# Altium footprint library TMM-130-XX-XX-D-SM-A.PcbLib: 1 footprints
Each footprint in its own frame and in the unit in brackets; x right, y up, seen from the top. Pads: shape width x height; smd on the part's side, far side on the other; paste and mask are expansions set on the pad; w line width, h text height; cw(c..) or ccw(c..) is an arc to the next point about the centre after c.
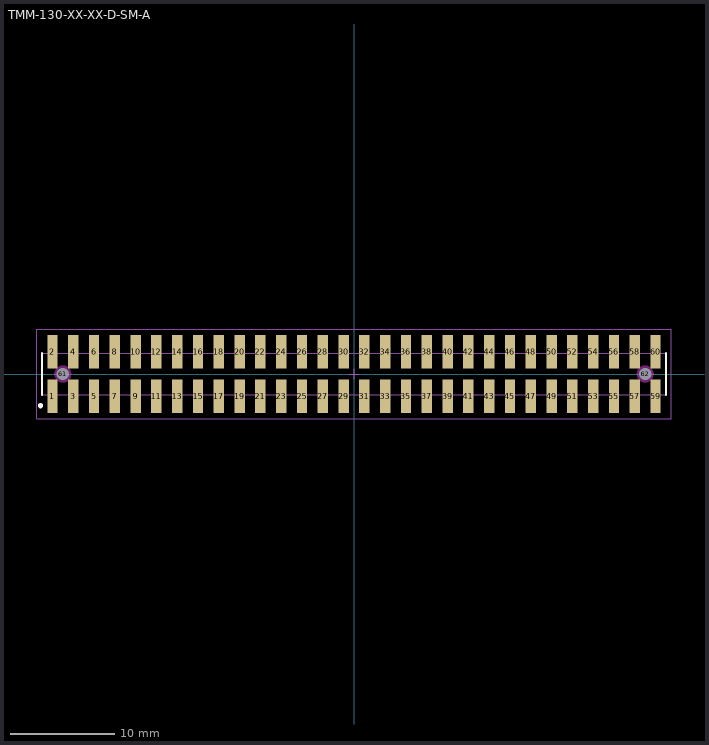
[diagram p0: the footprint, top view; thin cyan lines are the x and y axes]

## TMM-130-XX-XX-D-SM-A [mm] "2.00mm pitch, 60 pin, terminal strip; double row, w/alignment pins, SMT"
height 2.77
pads (62):
  rect 1x3.2 smd mask+0: 1(-29,-2.15) 2(-29,2.15) 3(-27,-2.15) 4(-27,2.15) 5(-25,-2.15) 6(-25,2.15) 7(-23,-2.15) 8(-23,2.15) 9(-21,-2.15) 10(-21,2.15) 11(-19,-2.15) 12(-19,2.15) 13(-17,-2.15) 14(-17,2.15) 15(-15,-2.15) 16(-15,2.15) 17(-13,-2.15) 18(-13,2.15) 19(-11,-2.15) 20(-11,2.15) 21(-9,-2.15) 22(-9,2.15) 23(-7,-2.15) 24(-7,2.15) 25(-5,-2.15) 26(-5,2.15) 27(-3,-2.15) 28(-3,2.15) 29(-1,-2.15) 30(-1,2.15) 31(1,-2.15) 32(1,2.15) 33(3,-2.15) 34(3,2.15) 35(5,-2.15) 36(5,2.15) 37(7,-2.15) 38(7,2.15) 39(9,-2.15) 40(9,2.15) 41(11,-2.15) 42(11,2.15) 43(13,-2.15) 44(13,2.15) 45(15,-2.15) 46(15,2.15) 47(17,-2.15) 48(17,2.15) 49(19,-2.15) 50(19,2.15) 51(21,-2.15) 52(21,2.15) 53(23,-2.15) 54(23,2.15) 55(25,-2.15) 56(25,2.15) 57(27,-2.15) 58(27,2.15) 59(29,-2.15) 60(29,2.15)
  round 1 hole 1.2 unplated mask+0: 61(-28,0) 62(28,0)
Top Overlay:
  circle w0.25: c-30.15,-3.05 r0.125
  lines w0.2: -30,-2 -30,2 ; 30,-2 30,2
Keep-Out Layer:
  pour cut-out: 28.807,0 28.779,0.209 28.699,0.403 28.57,0.571 28.403,0.699 28.209,0.779 28,0.807 27.791,0.779 27.596,0.699 27.429,0.571 27.301,0.403 27.22,0.209 27.193,0 27.22,-0.209 27.301,-0.403 27.429,-0.571 27.596,-0.699 27.791,-0.779 28,-0.807 28.209,-0.779 28.403,-0.699 28.57,-0.571 28.699,-0.403 28.779,-0.209
  pour cut-out: -27.193,0 -27.22,0.209 -27.301,0.403 -27.429,0.571 -27.596,0.699 -27.791,0.779 -28,0.807 -28.209,0.779 -28.403,0.699 -28.57,0.571 -28.699,0.403 -28.779,0.209 -28.807,0 -28.779,-0.209 -28.699,-0.403 -28.57,-0.571 -28.403,-0.699 -28.209,-0.779 -28,-0.807 -27.791,-0.779 -27.596,-0.699 -27.429,-0.571 -27.301,-0.403 -27.22,-0.209
Mechanical 12:
  lines w0.001: -30,-2 -30,2 30,2 30,-2 -30,-2
Mechanical 13:
  lines w0.1: -30,-2 -30,2 30,2 30,-2 -30,-2
  text ".Designator" at 0.127,-0.127 h1.52
Mechanical 15:
  lines w0.05: -0.5,0 0.5,0 ; 0,-0.5 0,0.5 ; -30.5,-4.3 -30.5,4.3 30.5,4.3 30.5,-4.3 -30.5,-4.3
